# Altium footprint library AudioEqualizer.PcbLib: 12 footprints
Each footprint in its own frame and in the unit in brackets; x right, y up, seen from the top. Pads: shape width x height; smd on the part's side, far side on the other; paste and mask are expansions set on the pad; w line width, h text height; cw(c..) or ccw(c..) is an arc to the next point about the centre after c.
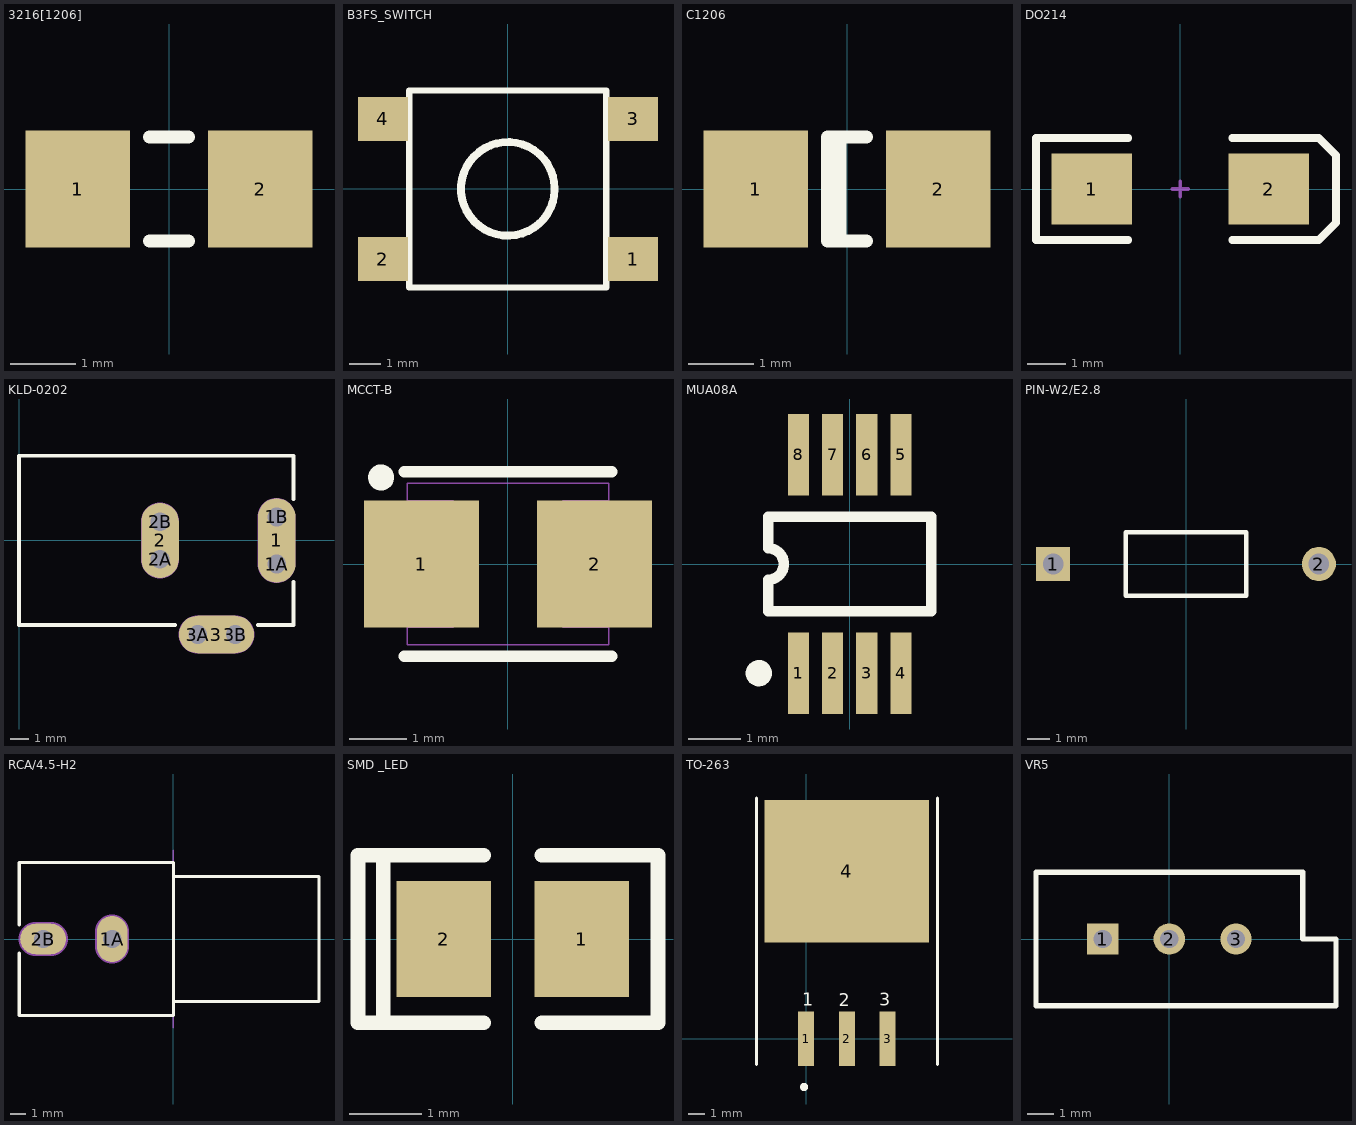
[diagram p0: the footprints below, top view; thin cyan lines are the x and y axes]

## 3216[1206] [mm]
pads (2):
  rect 1.6x1.8 smd: 1(-1.4,0) 2(1.4,0)
Top Overlay:
  lines w0.2: -0.3,-0.8 0.3,-0.8 ; -0.3,0.8 0.3,0.8

## B3FS_SWITCH [mm]
pads (4):
  rect 1.6x1.4 smd: 1(4.01,-2.25) 2(-4,-2.25) 3(4.01,2.24) 4(-4,2.24)
Top Overlay:
  circle w0.254: c0,0 r1.5
  lines w0.2: -3.16,-3.16 -3.16,3.15 3.15,3.15 3.15,-3.16 -3.16,-3.16

## C1206 [mm]
pads (2):
  rect 1.6x1.8 smd: 1(-1.4,0) 2(1.4,0)
Top Overlay:
  lines w0.2: -0.11,-0.8 -0.11,0.8 ; 0.3,-0.8 -0.3,-0.8 -0.3,0.8 0.3,0.8

## DO214 [mm]
pads (2):
  rect 2.1x1.85 smd: 1(-2.3,0) 2(2.3,0)
Top Overlay:
  lines w0.2: -1.35,-1.325 -3.75,-1.325 -3.75,1.325 -1.35,1.325 ; 1.35,-1.325 3.6,-1.325 4.05,-0.875 4.05,0.875 3.6,1.325 1.35,1.325
Mechanical 1:
  lines w0.1: -0.2,0 0.2,0 ; 0,-0.2 0,0.2

## KLD-0202 [mm]
pads (9):
  oval 2x4.5 all layers, no hole: 1(13.7,0)
  round 1.5 hole 1: 1A(13.7,-1.25) 1B(13.7,1.25) 2A(7.5,-1) 2B(7.5,1) 3A(9.5,-5) 3B(11.5,-5)
  oval 2x4 all layers, no hole: 2(7.5,0)
  oval 4x2 all layers, no hole: 3(10.5,-5)
Top Overlay:
  lines w0.2: 8.3,-4.5 0,-4.5 0,4.5 14.6,4.5 14.6,2.2 ; 12.7,-4.5 14.6,-4.5 14.6,-2.2
Mechanical 1:
  lines w1: 7.5,-1 7.5,1 ; 9.5,-5 11.5,-5 ; 13.7,-1.25 13.7,1.25
  text "Mech 2 - Clearance, move to internal plane if present" at 0.286,5.066 h0.3
  text "Mech 1 - Slot cut-out" at 0.286,5.566 h0.3
  text "Assign keep-out area to slot" at 0.286,6.566 h0.3
  text "Alert PCB fab to slot details" at 0.286,6.066 h0.3
Mechanical 2:
  lines w2.016: 7.5,-1 7.5,1 ; 9.5,-5 11.5,-5 ; 13.7,-1.25 13.7,1.25

## MCCT-B [mm]
pads (2):
  rect 2x2.2 smd: 1(-1.5,0) 2(1.5,0)
Top Overlay:
  circle w0.25: c-2.2,1.5 r0.1
  lines w0.2: -1.8,-1.6 1.8,-1.6 ; -1.8,1.6 1.8,1.6
Mechanical 15:
  lines w0.025: -1.75,-1.1 -0.95,-1.1 -0.95,1.1 -1.75,1.1 ; 1.75,-1.1 0.95,-1.1 0.95,1.1 1.75,1.1 ; -1.75,-1.4 1.75,-1.4 1.75,1.4 -1.75,1.4 -1.75,-1.4

## MUA08A [mm]
pads (8):
  rect 0.4x1.55 smd: 1(-0.975,-2.075) 2(-0.325,-2.075) 3(0.325,-2.075) 4(0.975,-2.075) 5(0.975,2.075) 6(0.325,2.075) 7(-0.325,2.075) 8(-0.975,2.075)
Top Overlay:
  circle w0.25: c-1.725,-2.075 r0.125
  lines w0.2: -1.55,-0.9 1.55,-0.9 1.55,0.9 -1.55,0.9 -1.55,0.3 cw(c-1.55,0) -1.55,-0.3 -1.55,-0.9

## PIN-W2/E2.8 [mm]
pads (2):
  rect 1.5x1.5 hole 0.9: 1(-5.825,0)
  round 1.5 hole 0.9: 2(5.825,0)
Top Overlay:
  lines w0.2: -2.65,-1.4 2.65,-1.4 2.65,1.4 -2.65,1.4 -2.65,-1.4

## RCA/4.5-H2 [mm]
pads (2):
  oval 2x3 hole 1.2: 1A(-4,0)
  oval 3x2 hole 1.2: 2B(-8.496,0)
Top Overlay:
  lines w0.2: -10.075,5 -0.018,5 ; -10.057,-0.92 -10.057,-5 0,-5 0,5 ; -10.057,0.92 -10.057,5 ; 0,-4.065 9.5,-4.065 9.5,4.065 0,4.065
Mechanical 1:
  lines w0.1: 0,-5.8 0,5.8
  lines w1.2: -8.996,0 -7.996,0 ; -4,-0.5 -4,0.5
  text "PCB Edge" at -0.333,-4.618 h0.25
  text "Alert PCB fab to slot details" at -10.057,7.842 h0.3
  text "Slot 1.2x2.2mm, PTH" at -10.057,7.342 h0.3
  text "Assign keep-out area to slot" at -10.057,8.342 h0.3
  text "Mech 1 - Slot cut-out" at -10.057,6.842 h0.3
  text "Mech 2 - Clearance, move to internal plane if present" at -10.057,6.342 h0.3
Mechanical 2:
  lines w2.216: -8.996,0 -7.996,0 ; -4,-0.5 -4,0.5

## SMD _LED [mm]
pads (2):
  rect 1.3x1.6 smd: 1(0.95,0) 2(-0.95,0)
Top Overlay:
  lines w0.2: -1.78,-1.15 -1.78,1.15 ; -0.4,-1.15 -2.13,-1.15 -2.13,1.15 -0.4,1.15 ; 0.4,-1.15 2,-1.15 2,1.15 0.4,1.15

## TO-263 [mm]
pads (4):
  rect 1x3.4 smd: 1(0,0) 2(2.54,0) 3(5.08,0)
  rect 10.25x8.9 smd: 4(2.54,10.45)
Top Overlay:
  circle w0.25: c-0.125,-3 r0.125
  lines w0.2: -3.1,-1.6 -3.1,15 ; 8.2,-1.6 8.2,15
  text "1" at -0.25,2.075 h0.8
  text "3" at 4.572,2.075 h0.8
  text "2" at 2.032,2.032 h0.8

## VR5 [mm]
pads (3):
  rect 1.2x1.2 hole 0.7: 1(-2.54,0)
  round 1.2 hole 0.7: 2(0,0) 3(2.54,0)
Top Overlay:
  lines w0.2: -5.08,-2.54 -5.08,2.54 5.08,2.54 5.08,0 6.35,0 6.35,-2.54 -5.08,-2.54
